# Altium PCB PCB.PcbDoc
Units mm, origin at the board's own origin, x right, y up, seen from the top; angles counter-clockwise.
Board outline 90 x 70 mm, 2 copper layers (Top Layer, Bottom Layer); 116 components, 91 nets, 451 pads, 231 vias.
Unrouted connection lines stored in the file: 2.
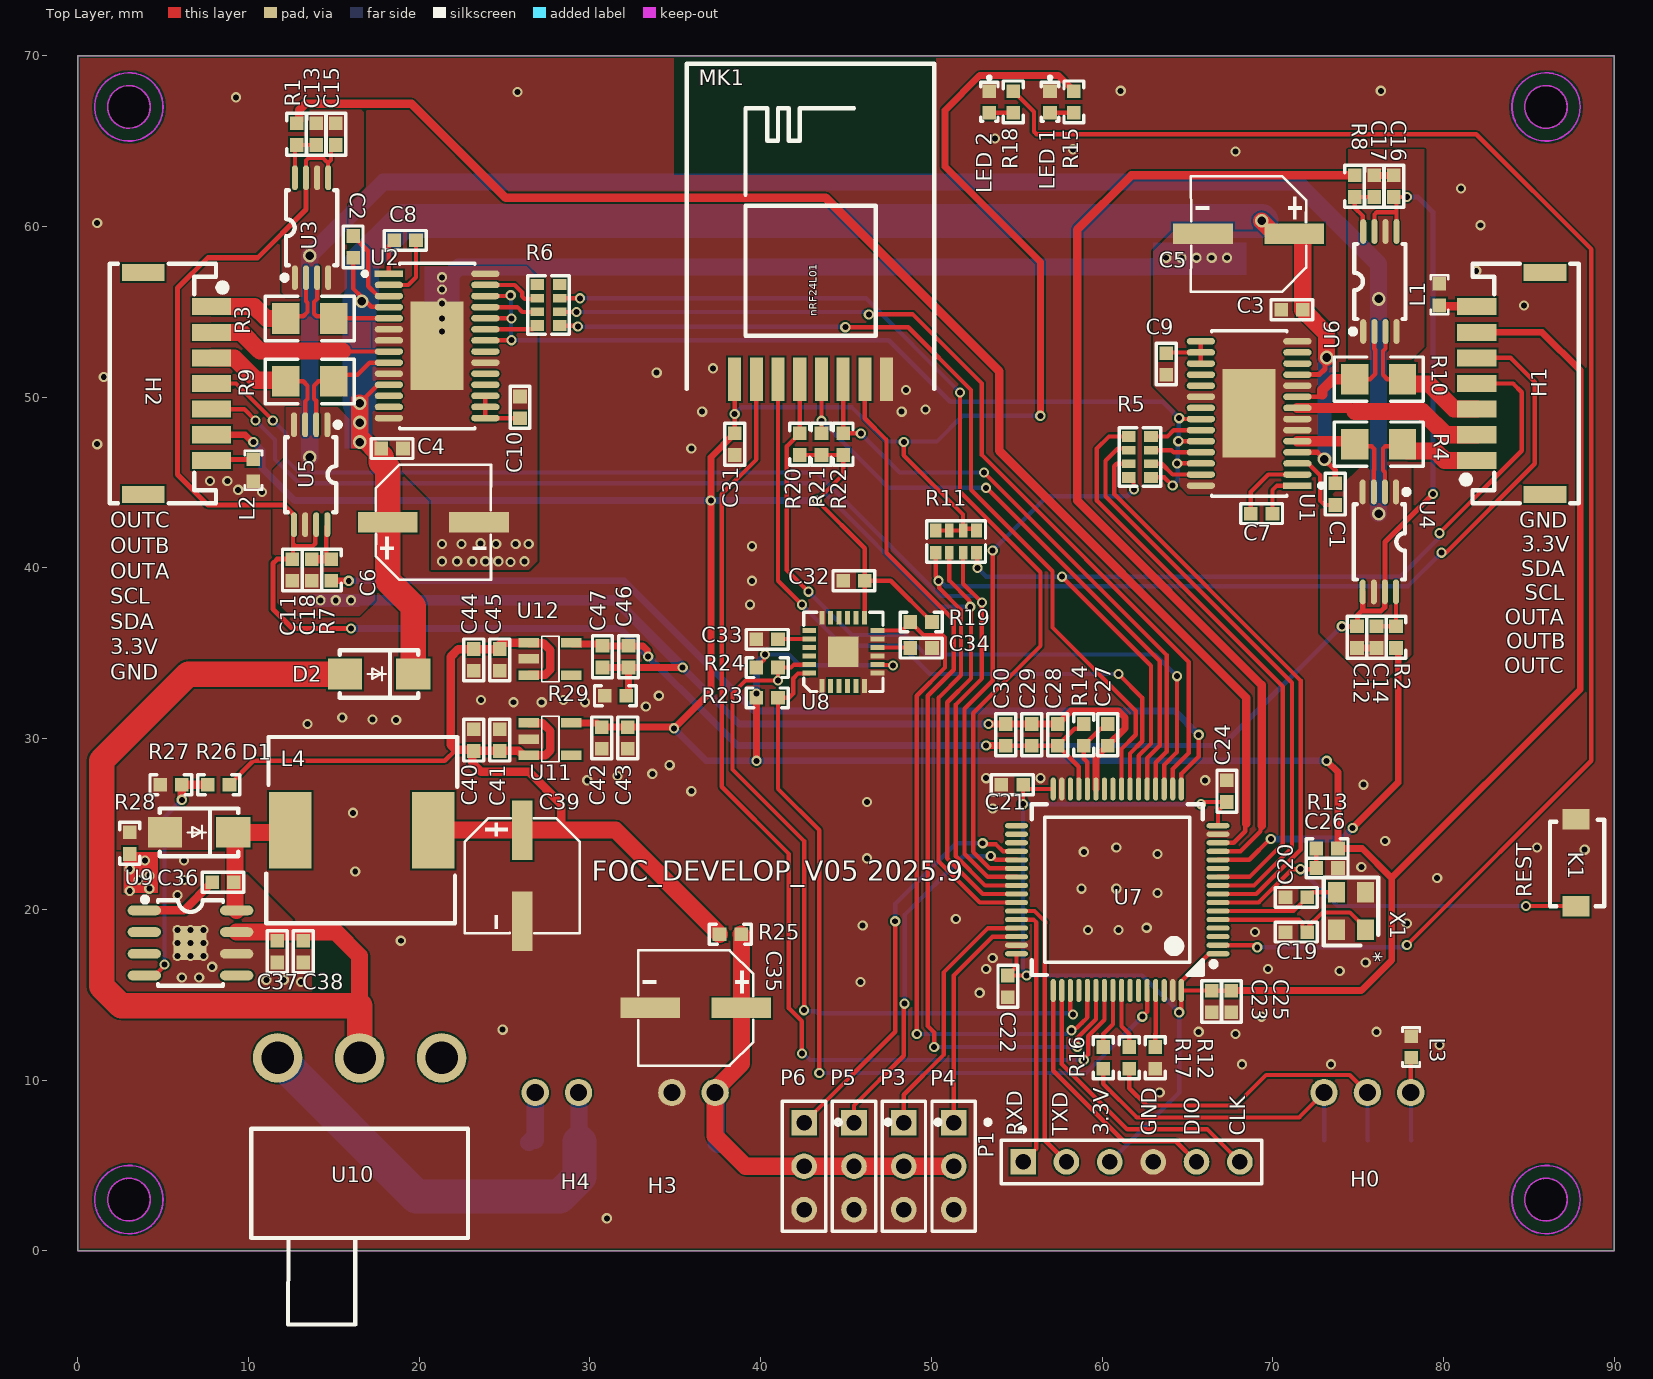
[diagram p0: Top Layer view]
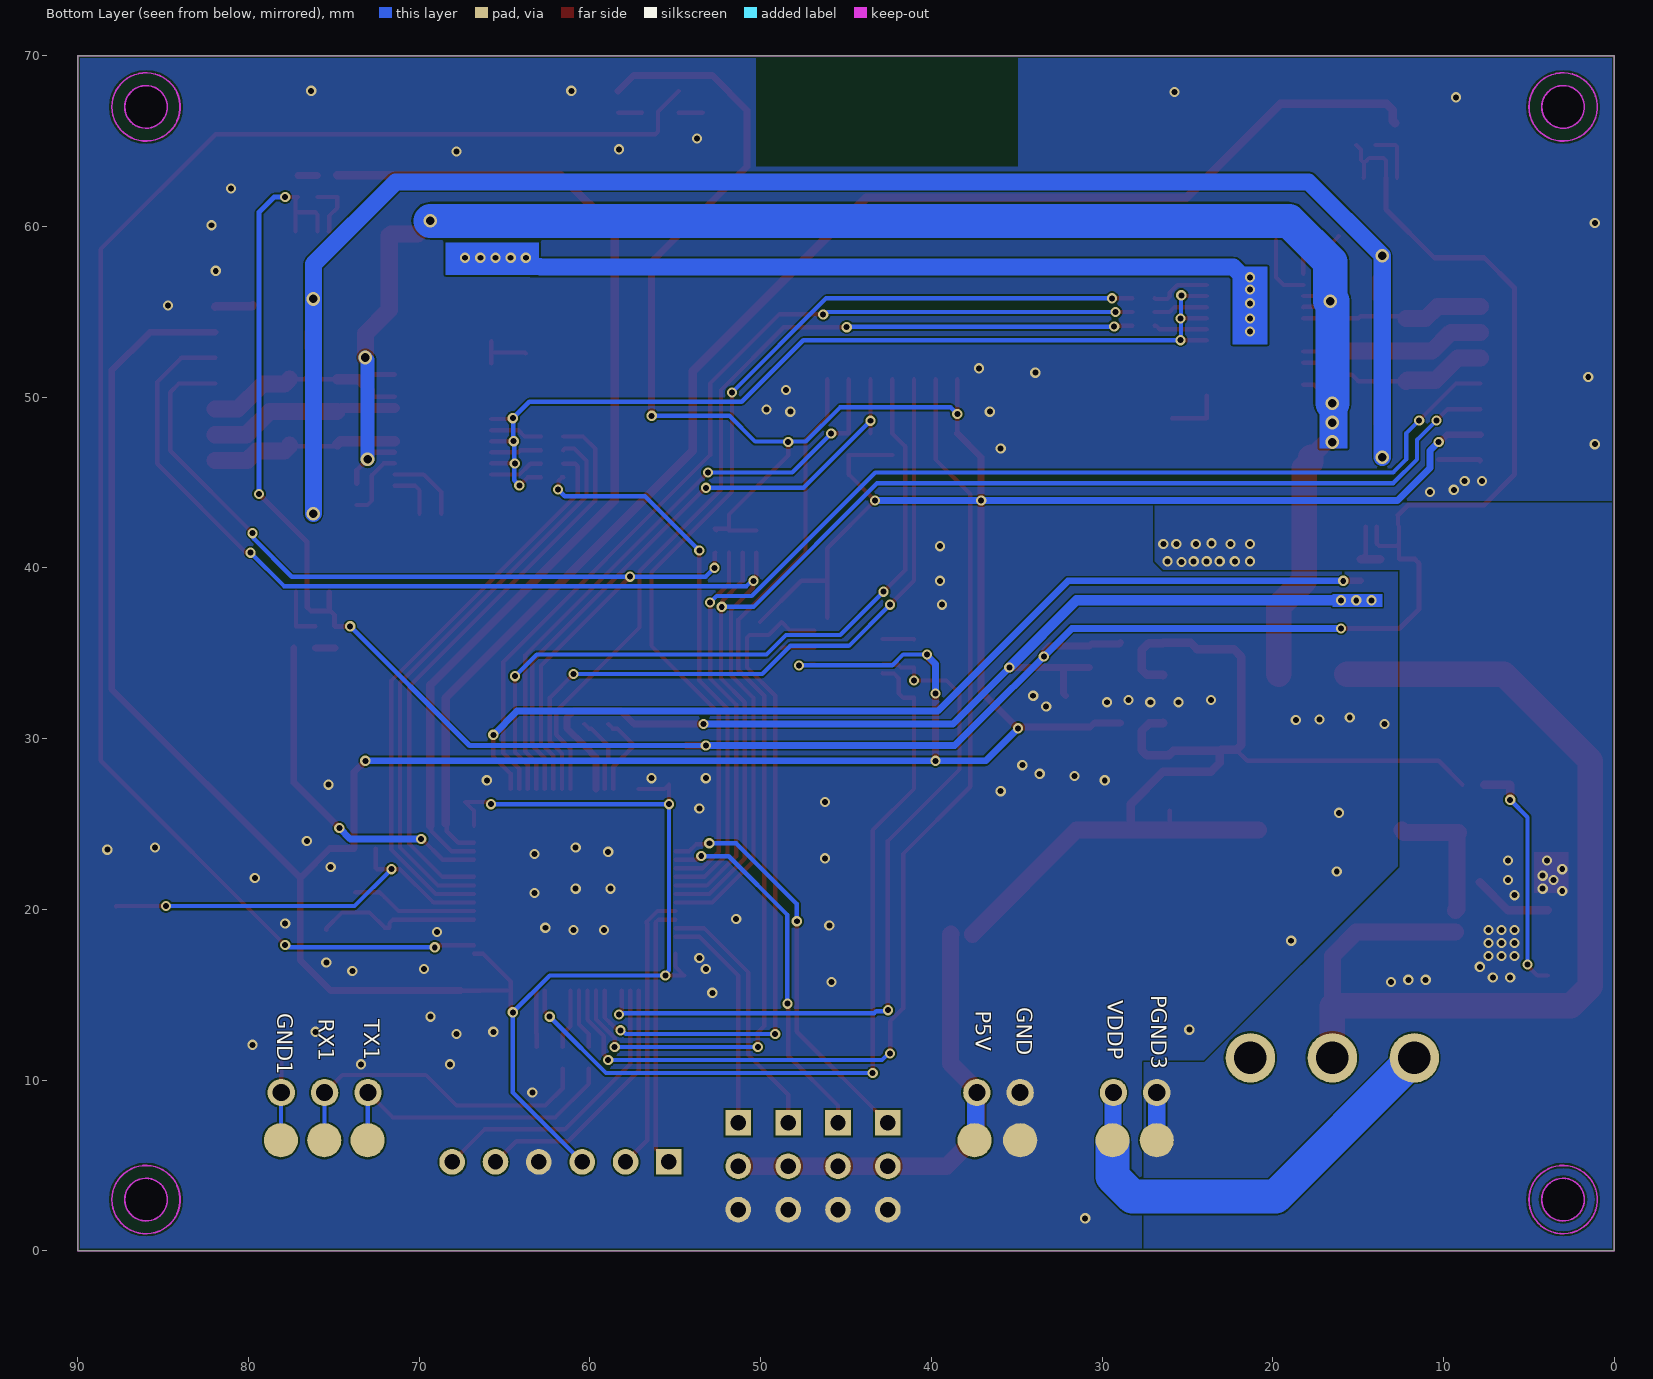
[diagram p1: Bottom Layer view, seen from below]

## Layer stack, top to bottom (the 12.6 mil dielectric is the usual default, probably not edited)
Top Solder: solder mask 0.0102, Solder Resist, Dk 3.5
Top Layer: signal copper 0.0356
Dielectric 1: dielectric 0.32, FR-4, Dk 4.8
Bottom Layer: signal copper 0.0356
Bottom Solder: solder mask 0.0102, Solder Resist, Dk 3.5

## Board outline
0,0 0,70 90,70 90,0
cut-out: 84.75,67 ccw(c86,67) 86,65.75 ccw(c86,67) 87.25,67 ccw(c86,67) 86,68.25 ccw(c86,67)
cut-out: 3,65.75 cw(c3,67) 1.75,67 cw(c3,67) 3,68.25 cw(c3,67) 4.25,67 cw(c3,67)
cut-out: 84.75,67 ccw(c86,67) 86,65.75 ccw(c86,67) 87.25,67 ccw(c86,67) 86,68.25 ccw(c86,67)
cut-out: 1.75,3 ccw(c3,3) 3,1.75 ccw(c3,3) 4.25,3 ccw(c3,3) 3,4.25 ccw(c3,3)
cut-out: 84.75,3 ccw(c86,3) 86,1.75 ccw(c86,3) 87.25,3 ccw(c86,3) 86,4.25 ccw(c86,3)

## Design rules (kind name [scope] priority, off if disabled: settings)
Clearance [All] p1: gap=0.1 ignorepadtopadclearanceinfootprint=FALSE except(0: Arc-Hole Track-Hole SMDPad-Hole THPad-Hole Via-Hole Fill-Hole Poly-Hole Region-Hole Text-Hole; 0.102: Arc-Arc Arc-Track Arc-SMDPad Arc-THPad Track-Track Track-SMDPad Track-THPad SMDPad-SMDPad SMDPad-THPad THPad-THPad; 0.127: Arc-Via Track-Via SMDPad-Via SMDPad-Text THPad-Via Via-Via; 0.254: Arc-Text Track-Text THPad-Text Via-Text Fill-Text Poly-Text Region-Text Text-Text)
HoleSize [All] p1: absolutevalues=TRUE maxlimit=30 minlimit=0.025 maxpercent=80.000 minpercent=20.000
HoleToHoleClearance [All] p1: gap=0.152 allowstackedmicrovias=TRUE
MinimumSolderMaskSliver [All] p1: minsoldermaskwidth=0
PlaneClearance [All] p1: clearance=0.254
PlaneConnect [All] p1: planeconnectstyle=Direct reliefexpansion=0.508 reliefentries=4 reliefconductorwidth=0.254 reliefairgap=0.254
PolygonConnect [All] p1: connectstyle=Direct reliefconductorwidth=0.254 reliefentries=4 polygonreliefangle="90 Angle" airgapwidth=0.254
RoutingVias [All] p1: holewidth=0.711 width=1.27 viastyle="Through Hole" minholewidth=0.3 minwidth=0.5 maxholewidth=30 maxwidth=30
SilkToSilkClearance [All] p1: silktosilkclearance=0
SilkToSolderMaskClearance [IsPad] p1: minsilkscreentomaskgap=0 clearancetoexposedcopper=TRUE
SolderMaskExpansion [All] p1: expansion=0.102 istentingtop=FALSE
Width [All] p1: maxlimit=3 minlimit=0.1 preferedwidth=0.254
23 further rules are at their usual default settings.

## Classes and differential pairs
component class Sheet3-power: C36 C37 C38 C39 C40 C41 C42 C43 C44 C45 C46 C47 D1 D2 H4 L4 PGND3 R26 R27 R28 R29 U9 U10 U11 U12 VDDP
component class Sheet2-sensor: C31 C32 C33 C34 C35 GND H3 MK1 P3 P4 P5 P5V P6 R19 R20 R21 R22 R23 R24 R25 U8
component class Sheet0-MCU: C19 C20 C21 C22 C23 C24 C25 C26 C27 C28 C29 C30 GND1 H0 K1 L3 "LED 1" "LED 2" P1 R12 R13 R14 R15 R16 R17 R18 RX1 TX1 U7 X1
component class Sheet1-driver: C1 C2 C3 C4 C5 C6 C7 C8 C9 C10 C11 C12 C13 C14 C15 C16 C17 C18 H1 H2 L1 L2 R1 R2 R3 R4 R5 R6 R7 R8 R9 R10 R11 U1 U2 U3 U4 U5 U6

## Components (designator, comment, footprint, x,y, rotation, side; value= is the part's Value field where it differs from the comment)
C1 "100nF" CC1608-0603 73.66,44.323 r90 top
C2 "100nF" CC1608-0603 16.129,58.801 r270 top
C3 "100NF" CC1608-0603 71.12,55.118 r180 top
C4 "100NF" CC1608-0603 18.415,46.99 r0 top
C5 "35V 100uF" CAP-SMD_D6.3 68.58,59.563 r180 top
C6 "35V 100uF" CAP-SMD_D6.3 20.831,42.672 r0 top
C7 "0.01uF" CC1608-0603 69.342,43.18 r0 top
C8 "0.01uF" CC1608-0603 19.177,59.182 r180 top
C9 "0.47UF" CC1608-0603 63.754,51.943 r270 top
C10 "0.47UF" CC1608-0603 25.908,49.403 r90 top
C11 "100nF" CC1608-0603 12.573,39.878 r270 top
C12 "100nF" CC1608-0603 74.93,35.941 r270 top
C13 "2.2nF" CC1608-0603 13.97,65.405 r270 top
C14 "2.2nF" CC1608-0603 76.073,35.941 r90 top
C15 "100nF" CC1608-0603 15.113,65.405 r90 top
C16 "100nF" CC1608-0603 77.089,62.357 r90 top
C17 "2.2nF" CC1608-0603 75.946,62.357 r270 top
C18 "2.2nF" CC1608-0603 13.716,39.878 r90 top
C19 "12PF" CC1608-0603 71.374,18.669 r0 top
C20 "12PF" CC1608-0603 71.374,20.701 r0 top
C21 "100NF" CC1608-0603 54.737,27.305 r0 top
C22 "100NF" CC1608-0603 54.483,15.494 r90 top
C23 "100NF" CC1608-0603 66.421,14.605 r90 top
C24 "100NF" CC1608-0603 67.31,26.924 r270 top
C25 "1UF" CC1608-0603 67.564,14.605 r90 top
C26 "100NF" CC1608-0603 73.18,22.424 r180 top
C27 "1UF" CC1608-0603 60.325,30.226 r90 top
C28 "10UF" CC1608-0603 57.404,30.226 r270 top
C29 "1UF" CC1608-0603 55.88,30.226 r270 top
C30 "100NF" CC1608-0603 54.356,30.226 r270 top
C31 "100NF" CC1608-0603 38.481,47.244 r270 top
C32 "100NF" CC1608-0603 45.466,39.243 r180 top
C33 "2.2UF" CC1608-0603 40.386,35.814 r180 top
C34 "100NF" CC1608-0603 49.403,35.306 r180 top
C35 "16V 220uF" CAP-SMD_D6.3 36.198,14.224 r180 top
C36 "0.01uf" CC1608-0603 8.509,21.59 r0 top
C37 "4.7uF 50V" CC1608-0603 11.684,17.526 r270 top
C38 "4.7uF 50V" CC1608-0603 13.208,17.526 r270 top
C39 "16V 220uF" CAP-SMD_D6.3 26.035,21.971 r270 top
C40 "2.2uf" CC1608-0603 23.201,29.914 r270 top
C41 "100nF" CC1608-0603 24.725,29.914 r270 top
C42 "22UF" CC1608-0603 30.694,30.041 r270 top
C43 "100NF" CC1608-0603 32.218,30.041 r270 top
C44 "2.2uf" CC1608-0603 23.201,34.613 r90 top
C45 "100nF" CC1608-0603 24.725,34.613 r90 top
C46 "22UF" CC1608-0603 32.258,34.798 r270 top
C47 "100NF" CC1608-0603 30.734,34.798 r270 top
D1 "B340A" "DO-214 AA" 7.112,24.511 r180 top
D2 "SS34" "DO-214 AA" 17.653,33.782 r180 top
GND "test" test#1 34.798,6.477 r90 bottom
GND1 "test" test#2 78.359,6.255 r180 bottom
H0 "Header_3P_Curved" Header_2_54_3PW 73,9.271 r0 top locked
H1 "ZH 1.5-7P" ZH1.5-7P 83.947,50.8 r90 top locked
H2 "ZH 1.5-7P" ZH1.5-7P 5.842,50.8 r270 top locked
H3 "Header_2P_Curved" Header_2_54_2PW 34.798,9.271 r0 top locked
H4 "Header_2P_Curved" Header_2_54_2PW 26.797,9.271 r0 top locked
K1 "KEY 3*4" "KEY 3*4" 87.757,20.173 r90 top
L1 "68nH 200mA" Inductor-0603 79.756,56.007 r90 top
L2 "68nH 200mA" Inductor-0603 10.287,45.72 r270 top
L3 "68nH 200mA" Inductor-0603 78.105,11.938 r90 top
L4 "22UH" Inductor-1040 12.446,24.638 r90 top
"LED 1" "LED 0603" "LED 0603" 56.951,67.294 r90 top
"LED 2" "LED 0603" "LED 0603" 53.395,67.294 r90 top
MK1 "GT-24-MINI" "GT24 _MINI" 38.481,51.054 r90 top locked
P1 "Header 6" HDR1X6 55.372,5.207 r0 top
P3 "Header 3" HDR1X3 48.387,7.493 r270 top
P4 "Header 3" HDR1X3 51.308,7.493 r270 top
P5 "Header 3" HDR1X3 45.466,7.493 r270 top
P5V "test" test#1 37.465,6.477 r90 bottom
P6 "Header 3" HDR1X3 42.545,7.493 r270 top
PGND3 "test" test#3 28.018,6.445 r0 bottom
R1 "22R" CR1608-0603 12.827,65.405 r270 top
R2 "22R" CR1608-0603 77.216,35.941 r90 top
R3 "0.01R" CR3216-1206 13.589,54.61 r180 top locked
R4 "0.01R" CR3216-1206 76.2,47.244 r0 top locked
R5 "0R" SMD_0603-8P 62.215,46.501 r90 top
R6 "0R" SMD_0603-8P 27.574,55.391 r270 top
R7 "22R" CR1608-0603 14.859,39.878 r90 top
R8 "22R" CR1608-0603 74.803,62.357 r270 top
R9 "0.01R" CR3216-1206 13.589,50.927 r0 top locked
R10 "0.01R" CR3216-1206 76.2,51.054 r180 top
R11 "4.7K" SMD_0603-8P 51.454,41.544 r180 top
R12 "10K" CR1608-0603 63.119,11.303 r90 top
R13 "10K" CR1608-0603 73.18,23.567 r0 top
R14 "10R" CR1608-0603 58.928,30.226 r90 top
R15 "2K" CR1608-0603 58.348,67.294 r90 top
R16 "22R" CR1608-0603 60.071,11.303 r270 top
R17 "22R" CR1608-0603 61.595,11.303 r270 top
R18 "2K" CR1608-0603 54.792,67.294 r90 top
R19 "10K" CR1608-0603 49.403,36.83 r0 top
R20 "10K" CR1608-0603 42.291,47.244 r90 top
R21 "10K" CR1608-0603 43.561,47.244 r90 top
R22 "10K" CR1608-0603 44.831,47.244 r90 top
R23 "10K" CR1608-0603 40.386,32.385 r0 top
R24 "10K" CR1608-0603 40.386,34.163 r0 top
R25 "0R" CR1608-0603 38.227,18.542 r0 top
R26 "10K 1%" CR1608-0603 8.255,27.305 r0 top
R27 "3.24K 1%" CR1608-0603 5.461,27.305 r0 top
R28 "0R" CR1608-0603 3.048,23.876 r270 top
R29 "0R" CR1608-0603 31.496,32.512 r180 top
RX1 "test" test#4 75.438,6.128 r180 bottom
TX1 "test" test#5 72.517,5.747 r180 bottom
U1 "DRV8313PWPR" HTSSOP-28 68.611,49.046 r180 top
U2 "DRV8313PWPR" HTSSOP-28 21.051,53 r0 top
U3 "INA240A1PWR" TSSOP-8 13.697,59.925 r0 top
U4 "INA240A1PWR" TSSOP-8 76.241,41.523 r180 top
U5 "INA240A1PWR" TSSOP-8 13.645,45.46 r180 top locked
U6 "INA240A1PWR" TSSOP-8 76.271,56.775 r0 top
U7 "STM32G431RBT6" LQFP-64 60.889,21.151 r90 top
U8 "MPU6050" "QFN24 - duplicate" 44.843,35.084 r90 top locked
U9 "TPS5430DDAR" SOIC-8-E 6.604,18.034 r270 top
U10 "HX SS12D10G4" SW-TH_3P-SS12D06 16.51,11.303 r0 top locked
U11 "SPX3819M5-L-3.3/TR" SOT23-5 26.416,29.019 r90 top
U12 "SPX3819M5-L-3.3/TR" SOT23-5 26.416,33.718 r90 top
VDDP "test" test#6 29.21,6.572 r0 bottom
X1 "3225_8M" XTAL-3225 73.738,18.796 r90 top

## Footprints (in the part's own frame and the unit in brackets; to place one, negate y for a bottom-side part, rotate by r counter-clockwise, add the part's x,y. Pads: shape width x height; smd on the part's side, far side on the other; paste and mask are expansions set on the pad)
CAP-SMD_D6.3 [mm] "直径6.3mm固态电容"
  rect 3.5x1.2 smd paste+0 mask+0.051: 1(-2.67,0) 2(2.67,0)
  silkscreen extent -3.38,-3.38 3.38,3.38, body extent -3.65,-3.3 3.65,3.3, height 5.9
CC1608-0603 [mm]
  rect 0.8x0.8 smd: 1(-0.635,0) 2(0.635,0)
  silkscreen extent -1.23,-0.58 1.23,0.58, body extent -0.8,-0.4 0.8,0.4, height 0.3
CR1608-0603 [mm]
  rect 0.8x0.8 smd: 1(-0.635,0) 2(0.635,0)
  silkscreen extent -1.23,-0.58 1.23,0.58, body extent -0.8,-0.4 0.8,0.4, height 0.45
CR3216-1206 [mm]
  rect 1.6x1.8 smd: 1(-1.4,0) 2(1.4,0)
  silkscreen extent -2.6,-1.3 2.6,1.3, body extent -1.6,-0.8 1.6,0.8, height 0.6
"DO-214 AA" [mm] "SMB"
  rect 2x1.8 smd: 1(-2,0) 2(2,0)
  silkscreen extent -2.3,-1.4 2.3,1.4, body extent -2.83,-1.8 2.57,1.8, height 2.4
"GT24 _MINI" [mil]
  rect 100x30 smd paste+0 mask+2: 1(0,0) 2(0,-50) 3(0,-100) 4(0,-150) 5(0,-200) 6(0,-250) 7(0,-300) 8(0,-350)
  silkscreen extent -23,-460 728,110, body extent -23,-460 728,110, height 79
HDR1X3 [mm] "Connector; Header; 3 Position"
  rect 1.5x1.5 hole 0.9: 1(0,0)
  round 1.5 hole 0.9: 2(2.54,0) 3(5.08,0)
  silkscreen extent -1.27,-1.27 6.35,2.14, body extent -1.27,-1.27 6.35,1.27, height 8.54
HDR1X6 [mm] "Connector; Header; 6 Position"
  rect 1.5x1.5 hole 0.9: 1(0,0)
  round 1.5 hole 0.9: 2(2.54,0) 3(5.08,0) 4(7.62,0) 5(10.16,0) 6(12.7,0)
  silkscreen extent -1.27,-1.27 13.97,2.04, body extent -1.27,-1.27 13.97,1.27, height 8.54
Header_2_54_2PW [mm] "弯的排针"
  round 1.6 hole 1: 1(0,0) 2(2.54,0)
  body extent -2.52,-7.47 5.18,0.38, height 5.8
Header_2_54_3PW [mm] "3P弯针"
  round 1.6 hole 1: 1(0,0) 2(2.54,0) 3(5.08,0)
  body extent -2.6,-7.48 7.62,0.38, height 5.8
HTSSOP-28 [mm]
  rect 1.655x0.381 smd paste+0 mask+0: 1(-2.825,4.225)
  rrect100% 1.655x0.381 smd paste+0 mask+0: 2(-2.825,3.575) 3(-2.825,2.925) 4(-2.825,2.275) 5(-2.825,1.625) 6(-2.825,0.975) 7(-2.825,0.325) 8(-2.825,-0.325) 9(-2.825,-0.975) 10(-2.825,-1.625) 11(-2.825,-2.275) 12(-2.825,-2.925) 13(-2.825,-3.575) 14(-2.825,-4.225) 15(2.825,-4.225) 16(2.825,-3.575) 17(2.825,-2.925) 18(2.825,-2.275) 19(2.825,-1.625) 20(2.825,-0.975) 21(2.825,-0.325) 22(2.825,0.325) 23(2.825,0.975) 24(2.825,1.625) 25(2.825,2.275) 26(2.825,2.925) 27(2.825,3.575) 28(2.825,4.225)
  rect 3.1x5.18 smd paste-1000 mask+0: 29(0,0)
  silkscreen extent -4.35,-4.85 2.2,4.85, body extent -3.9,-5.1 3.9,5.1, height 0.25
Inductor-0603 [mm]
  rect 0.8x0.8 smd: 1(-0.635,0) 2(0.635,0)
  silkscreen extent -1.14,-0.51 1.14,0.51, body extent -0.8,-0.43 0.8,0.43, height 0.48
Inductor-1040 [mm]
  rect 4.5x2.5 smd: 1(0,0) 2(0,-8.382)
  silkscreen extent -5.46,-9.78 5.46,1.4, body extent -5,-9.39 5,1.01, height 3.9
"KEY 3*4" [mm]
  rect 1.2x1.6 smd: 1(0,0) 2(5.1,0)
  silkscreen extent 0,-1.65 5.08,1.52, body extent 0.25,-1.71 4.7,1.46, height 2.01
"LED 0603" [mm]
  rect 0.8x0.8 smd: 1(-0.635,0) 2(0.635,0)
  silkscreen extent -1.14,-0.51 1.48,0.51, body extent -0.8,-0.4 0.8,0.4, height 0.6
LQFP-64 [mm]
  oval 0.3x1.35 smd paste+0 mask+0.051: 1(-3.75,-5.9) 2(-3.25,-5.9) 3(-2.75,-5.9) 4(-2.25,-5.9) 5(-1.75,-5.9) 6(-1.25,-5.9) 7(-0.75,-5.9) 8(-0.25,-5.9) 9(0.25,-5.9) 10(0.75,-5.9) 11(1.25,-5.9) 12(1.75,-5.9) 13(2.25,-5.9) 14(2.75,-5.9) 15(3.25,-5.9) 16(3.75,-5.9) 33(3.75,5.9) 34(3.25,5.9) 35(2.75,5.9) 36(2.25,5.9) 37(1.75,5.9) 38(1.25,5.9) 39(0.75,5.9) 40(0.25,5.9) 41(-0.25,5.9) 42(-0.75,5.9) 43(-1.25,5.9) 44(-1.75,5.9) 45(-2.25,5.9) 46(-2.75,5.9) 47(-3.25,5.9) 48(-3.75,5.9)
  oval 1.35x0.3 smd paste+0 mask+0.051: 17(5.9,-3.75) 18(5.9,-3.25) 19(5.9,-2.75) 20(5.9,-2.25) 21(5.9,-1.75) 22(5.9,-1.25) 23(5.9,-0.75) 24(5.9,-0.25) 25(5.9,0.25) 26(5.9,0.75) 27(5.9,1.25) 28(5.9,1.75) 29(5.9,2.25) 30(5.9,2.75) 31(5.9,3.25) 32(5.9,3.75) 49(-5.9,3.75) 50(-5.9,3.25) 51(-5.9,2.75) 52(-5.9,2.25) 53(-5.9,1.75) 54(-5.9,1.25) 55(-5.9,0.75) 56(-5.9,0.25) 57(-5.9,-0.25) 58(-5.9,-0.75) 59(-5.9,-1.25) 60(-5.9,-1.75) 61(-5.9,-2.25) 62(-5.9,-2.75) 63(-5.9,-3.25) 64(-5.9,-3.75)
  silkscreen extent -5,-5.79 5,5, body extent -6.05,-6.12 6.1,6.02, height 1.62
"QFN24 - duplicate" [mm]
  rect 0.8x0.3 smd: 1(-2,1.25) 2(-2,0.75) 3(-2,0.25) 4(-2,-0.25) 5(-2,-0.75) 6(-2,-1.25) 13(2,-1.25) 14(2,-0.75) 15(2,-0.25) 16(2,0.25) 17(2,0.75) 18(2,1.25)
  rect 1.8x1.8 smd: 1(0.005,0)
  rect 0.3x0.8 smd: 7(-1.25,-2) 8(-0.75,-2) 9(-0.25,-2) 10(0.25,-2) 11(0.75,-2) 12(1.25,-2) 19(1.25,2) 20(0.75,2) 21(0.25,2) 22(-0.25,2) 23(-0.75,2) 24(-1.25,2)
  silkscreen extent -2.32,-2.32 2.32,2.32, body extent -2,-2 2.01,2, height 0.9
SMD_0603-8P [mm]
  rect 0.65x0.8 smd paste+0 mask+0.051: 1(-1.2,-0.65) 4(1.2,-0.65) 5(1.2,0.65) 8(-1.2,0.65)
  rect 0.5x0.8 smd paste+0 mask+0.051: 2(-0.4,-0.65) 3(0.4,-0.65) 6(0.4,0.65) 7(-0.4,0.65)
  silkscreen extent -1.71,-1.22 1.71,1.22, body extent -1.6,-0.8 1.6,0.8, height 0.5
SOIC-8-E [mil]
  oval 22.38x76.78 smd paste+0 mask+2: 1(-75,-106.5) 2(-25,-106.5) 3(25,-106.5) 4(75,-106.5) 5(75,106.5) 6(25,106.5) 7(-25,106.5) 8(-75,106.5)
  rect 78.74x76.78 smd paste+0 mask+2: 9(0,-1)
  silkscreen extent -106,-111 98,75, body extent -98,-125 98,120, height 69
SOT23-5 [mm] "适用于MIC5205"
  rect 0.55x1.2 smd: 1(1.905,0) 2(0.955,0) 3(0.005,0) 4(0.005,-2.5) 5(1.905,-2.5)
  silkscreen extent -0.38,-1.78 2.29,-0.76, body extent -0.6,-2.82 2.5,0.38, height 1.45
SW-TH_3P-SS12D06 [mm]
  round 2.9 hole 1.9 paste+0 mask+0.051: 1(-4.8,0) 2(0,0) 3(4.8,0)
  silkscreen extent -6.35,-15.62 6.35,-4.15, body extent -6.35,-15.68 6.35,-4.19, height 6.7
test#1 [mm]
  round 2 smd: 0(0,0)
test#2 [mm]
  round 2 smd: 0(0.259,0.222)
test#3 [mm]
  round 2 smd: 0(-1.221,-0.032)
test#4 [mm]
  round 2 smd: 0(-0.122,0.349)
test#5 [mm]
  round 2 smd: 0(-0.503,0.73)
test#6 [mm]
  round 2 smd: 0(0.176,0.095)
TSSOP-8 [mm]
  oval 0.353x1.454 smd: 1(-0.975,-2.927) 2(-0.325,-2.927) 3(0.325,-2.927) 4(0.975,-2.927) 5(0.975,2.927) 6(0.325,2.927) 7(-0.325,2.927) 8(-0.975,2.927)
  silkscreen extent -1.73,-3.08 1.5,2.2, body extent -1.43,-3.17 1.57,3.11, height 1.09
XTAL-3225 [mm]
  rect 1.2x1 smd: 1(0,-1.7) 2(2.2,-1.7) 3(2.2,0) 4(0,0)
  silkscreen extent -0.91,-2.44 3.07,0.76, body extent -0.43,-2.15 2.77,0.35, height 0.61
ZH1.5-7P [mm]
  rect 1x2.3 smd paste+0 mask+0.05: 1(-4.5,2) 2(-3,2) 3(-1.5,2) 4(0,2) 5(1.5,2) 6(3,2) 7(4.5,2)
  rect 1x2.5 smd paste+0 mask+0.05: 8(6.5,-2) 9(-6.5,-2)
  silkscreen extent -7.02,-3.97 7.02,3.04, body extent -6.96,-4.36 6.96,2.69, height 4

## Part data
C1 C2 C3 C4 C7 C8 C9 C10 C11 C12 C13 C14 C15 C16 C17 C18 C19 C20 C21 C22 C23 C24 C25 C26 C27 C28 C29 C30 C40 C41 C44 C45: library part "Cap Chip 0603", "0603封装的电容"
C5 C6 C35 C39: library part "Cap ECAP SMD", "铝点解电容", BOM_Manufacturer=PANASONIC, BOM_Manufacturer Part=EEEFP1C681AP
C31 C32 C33 C34 C36 C37 C38 C42 C43 C46 C47: library part "Chip capacitor", "贴片电容"
D1: "40V 3A 550mV@3A", BOM_JLCPCB Part Class="Extended Part", BOM_Manufacturer=MDD
D2: "肖特基二极管"
GND GND1 P5V PGND3 RX1 TX1 VDDP: "测试点"
H0: "弯的3P排针"
H1 H2: "ZH1.5-7P 间距1.5的贴片连接座"
H3 H4: "弯的2P排针"
K1: "轻触开关按键"
L1 L2 L3: library part Inductor-0603, "贴片电感 0603封装"
L4: library part Inductor-1040, "1040封装 一体成型 贴片 功率电感"
MK1: "工业级GT-24数传无线模块 2.4G NRF24L01&PA+LNA", JLCPCB Part Class="Extended Part", Manufacturer=Ashining(泽耀科技), Manufacturer Part=AS01-ML01S
P1: "Header, 6-Pin"
P3 P4 P5 P6: "Header, 3-Pin"
R1 R2 R7 R8 R12 R13 R14 R15 R16 R17 R18 R28 R29: library part "Resistor Chip 0603", "0603封装电阻"
R3 R4 R9 R10: library part "Resistor Chip 1206", "1206封装电阻"
R5 R6 R11: library part "Resistor Chip 0603_1206", "0603封装电阻"
R19 R20 R21 R22 R23 R24 R25 R26 R27: library part "Chip resistor", "贴片电阻"
U1 U2: library part DRV8313, "独立控制的半 H 桥驱动器,主要用于驱动一个三项无刷电机IC MOTOR DRIVER 8V-60V 28HTSSOP", Case/Package=HTSSOP, Max Operating Temperature=125°C, Max Supply Voltage=60V, Min Operating Temperature=-40°C, Min Supply Voltage=8V, Output Current=1.75A, Package Quantity=2000
U3 U4 U5 U6: "超精密电流检测放大器"
U7: JLCPCB Part Class="Extended Part", Manufacturer=ST(意法半导体)
U8: "陀螺仪"
U9: "宽电压DCDC降压IC"
U10: library part SW-TH_3P-SS12D06, BOM_JLCPCB Part Class="Extended Part", BOM_Manufacturer=hanxia(韩下)
U11 U12: "LDO 3.3V , SOT-23-5 500ma"
X1: library part "XTAL 3225", "3225封装的晶振"

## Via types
v1: diameter 0.6, hole 0.35, Top Layer to Bottom Layer, tented both sides, 220 vias
v2: diameter 0.8, hole 0.5, Top Layer to Bottom Layer, tented both sides, 11 vias

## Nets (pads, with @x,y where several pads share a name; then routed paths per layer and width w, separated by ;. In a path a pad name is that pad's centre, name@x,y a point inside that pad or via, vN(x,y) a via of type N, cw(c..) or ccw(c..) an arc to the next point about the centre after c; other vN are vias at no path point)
3.3V: C21.2 C22.2 C23.2 C24.2 C25.2 C31.1 C32.1 C42.1 C43.1 H1.6 H2.6 MK1.1 P1.3 R11.1 R11.2 R11.3 R11.4 R13.2 R15.2 R19.2 R20.1 R21.1 R22.1 R23.1 R24.1 U7.1 U7.16 U7.32 U7.48 U7.64 U8.8 U8.13 U11.5 | length 318.9
  Top Layer w0.254: C31.1 MK1.1 ; R24.1 40.193,34.605 ; R20.1 R21.1 R22.1 44.831,45.466 v1(43.307,43.942) 46.101,41.148 C32.1 ; U8.13 46.093,39.235 C32.1 ; U8.8 47.094,34.334 47.116,34.312 47.73,34.312 v1(47.752,34.29) ; v1(48.387,47.371) 48.387,46.591 51.854,43.124 51.854,42.342 51.905,42.291 52.705,42.291 R11.1@52.608,42.194 ; R19.2 47.625,39.243 C32.1 ; R11.4 R11.3 R11.2 ; U7.48 54.989,16.635 C22.2 v1(55.58,16.129) ; v1(55.372,26.162) C21.2 55.626,27.051 U7.32 ; v1@64.639,14.186 U7.64 ; v1@66.007,26.289 C24.2 66.789,25.768 U7.16 ; U7.1 66.264,17.401 64.639,15.776 U7.64 ; C25.2 C23.2 66.41,15.251 U7.64
  Top Layer w0.4: H2.6 9.804,47.8 10.233,47.371 v1(10.287,47.371) ; U11.5 30.445,30.924 C42.1 34.802,30.676 34.871,30.607 v1(34.925,30.607) 37.084,32.766 37.084,46.482 C31.1 ; v1(39.751,28.702) R23.1 v1(39.751,32.639) ; v1@56.388,48.895 56.388,57.912 50.8,63.5 50.8,66.802 52.832,68.834 57.443,68.834 R15.2 ; C25.2 75.184,15.24 76.962,17.018 76.962,21.844 ; v1(73.152,28.702) 73.815,28.039 R13.2 75.239,23.567 76.962,21.844 ; H1.6 85.773,53.8 88.011,51.562 88.011,32.893 76.962,21.844
  Bottom Layer w0.254: v1(38.481,49.022) 38.862,49.403 45.356,49.403 47.356,47.402 50.323,47.402 51.832,48.911 v1(56.382,48.911) ; v1(40.259,34.925) 41.656,34.925 42.291,34.29 v1(47.752,34.29) ; v1(55.58,16.129) 55.58,16.223 55.372,16.431 v1(55.372,26.162) v1(65.786,26.162) ; v1@55.626,16.129 62.357,16.129 v1(64.516,13.97) 64.516,9.271 P1.3
  Bottom Layer w0.4: v1(10.287,47.371) 10.795,46.863 10.795,45.847 12.7,43.942 v1(37.084,43.942) ; v1(34.925,30.607) 36.83,28.702 v1(73.152,28.702) ; v1@37.118,43.942 v1(43.307,43.942) ; v1(39.751,32.639) 39.751,34.363 40.259,34.871 v1(40.259,34.925)
5V: C39.1 C40.2 C41.2 C44.2 C45.2 L4.2 R25.1 R26.2 U11.1 U11.3 U12.1 U12.3 | length 65.9
  Top Layer w0.254: R26.2 10.287,28.702 21.502,28.702 22.137,29.337 ; C39.1 C39.1@26.035,25.791
  Top Layer w0.5: U11.1 26.441,30.899 27.228,30.899 27.686,30.441 27.686,29.317 27.393,29.025 U11.3 26.091,29.025 25.837,29.279 C41.2 C40.2 C40.2@23.114,29.192 ; U12.3 26.441,33.749 27.393,33.749 27.686,34.041 27.686,35.179 27.267,35.598 26.441,35.598 U12.1 24.821,35.623 24.446,35.248 C44.2 22.294,35.248 21.844,34.798 21.844,29.63 22.137,29.337 23.051,29.337 23.114,29.274 C40.2@23.114,29.192 ; 28.321,24.641 28.321,26.162 26.416,28.067 23.622,28.067 23.114,28.575 C40.2@23.114,29.192
  Top Layer w1: L4.2 26.032,24.638 C39.1 28.321,24.641 31.493,24.641 R25.1
5V_M: C35.1 H3.2 P3.2 P4.2 P5.2 P5V.0 P6.2 R25.2 | length 30.3
  Top Layer w1: R25.2 38.868,18.536 C35.1 38.868,10.963 37.338,9.433 H3.2 37.338,6.731 39.116,4.953 P6.2 P5.2 P3.2 P4.2
  Bottom Layer w1: H3.2 37.401,9.207 37.401,6.286 P5V.0@37.465,6.223
ADC1_IN1: R2.1 U7.12 | length 20.3
  Top Layer w0.254: U7.12 68.621,22.901 69.843,24.123 v1(69.879,24.123)
  Top Layer w0.4: v1(74.676,24.765) 77.343,27.432 R2.1@77.343,35.306
  Bottom Layer w0.4: v1(69.879,24.123) 69.887,24.13 74.038,24.13 74.673,24.765 v1(74.676,24.765)
ADC1_IN2: R8.1 U7.13 | length 60.3
  Top Layer w0.254: U7.13 68.105,23.401 69.276,24.572 69.276,24.826 69.342,24.892
  Top Layer w0.5: 69.342,24.892 69.342,33.147 58.547,43.942 58.547,59.817 61.722,62.992 R8.1
ADC1_IN3: R1.1 U7.14 | length 83.3
  Top Layer w0.254: U7.14 67.716,23.901 68.387,24.572 68.387,24.953 68.453,25.019
  Top Layer w0.5: R1.1 12.977,66.19 12.977,66.825 13.335,67.183 19.558,67.183 25.063,61.678 43.815,61.678 53.975,51.518 53.975,46.863 68.453,32.385 68.453,25.019
ADC1_IN4: R7.1 U7.17 | length 58.1
  Top Layer w0.254: U7.17 64.639,27.936 65.659,28.956 v1(65.659,30.226)
  Top Layer w0.4: R7.1 v1(15.875,39.243)
  Bottom Layer w0.4: v1(15.875,39.243) 32.004,39.243 39.624,31.623 64.262,31.623 v1(65.659,30.226)
AGND: C11.2 C12.2 C13.1 C14.1 C15.2 C16.2 C17.1 C18.1 C27.1 C28.1 C29.1 C30.1 C46.2 C47.2 R29.1 U3.1 U3.4 U3.6 U4.1 U4.4 U4.6 U5.1 U5.4 U5.6 U6.1 U6.4 U6.6 U7.27 | length 155.2
  Top Layer w0.4: C47.2 C46.2 ; R29.1 32.258,32.639 C46.2 ; v1(35.433,34.163) C46.2 ; v1(53.34,30.861) C30.1 C29.1 C28.1 58.166,31.623 60.96,31.623 61.341,31.242 61.341,30.607 C27.1 59.639,28.905 U7.27 ; C12.2 C14.1 ; C17.1 C16.2
  Bottom Layer w0.4: v1(35.433,34.163) 38.735,30.861 v1(53.34,30.861)
  Bottom Layer w0.6: v1(16.002,38.1) 31.496,38.1 v1(35.433,34.163)
  Bottom Layer w1: v2(13.589,46.482) v2(13.589,58.293) 17.907,62.611 71.374,62.611 76.2,57.785 v2(76.2,55.753) v2(76.2,43.18)
  other v1: 14.224,38.1 15.113,38.1
BOOT0: R12.2 U7.61 | length 3.3
  Top Layer w0.254: R12.2 63.119,12.7 63.139,12.72 U7.61
DRV_EN: R5.8 U7.39 | length 32.7
  Top Layer w0.254: v1(53.594,41.021) 53.594,33.401 51.943,31.75 51.943,23.255 53.297,21.901 U7.39 ; R5.8 61.64,45.301 61.838,45.103 61.838,44.625 v1(61.867,44.596)
  Bottom Layer w0.254: v1(53.594,41.021) 56.769,44.196 61.468,44.196 v1(61.867,44.596)
GND: "LED 1.2" "LED 2.2" C19.1 C20.1 C21.1 C22.1 C23.1 C24.1 C25.1 C26.1 C31.2 C32.2 C33.2 C34.1 C35.2 C39.2 C40.1 C41.1 C42.2 C43.2 C44.1 C45.1 D1.2 GND.0 H3.1 K1.2 L1.2 L2.2 L3.2 MK1.8 P1.4 P3.3 P4.3 P5.3 P6.3 R12.1 R27.1 R28.1 R29.2 U7.15 U7.31 U7.47 U7.63 U8.1 U8.6 U8.7 U8.9 U8.11 U8.18 U11.2 U12.2 X1.2 X1.4
  other v1: 30.988,1.905 63.373,9.271 68.199,10.922 73.406,10.922 79.756,12.065 67.818,12.7 65.659,12.827 76.073,12.827 24.892,12.954 69.342,13.716 52.832,15.113 45.847,15.748 73.914,16.383 53.213,16.51 69.723,16.51 75.438,16.891 53.594,17.145 18.923,18.161 68.961,18.669 59.182,18.796 60.96,18.796 62.611,18.923 45.974,19.05 77.851,19.177 51.435,19.431 63.246,20.955 58.801,21.209 60.833,21.209 79.629,21.844 16.256,22.225 75.184,22.479 46.228,22.987 63.246,23.241 58.928,23.368 88.265,23.495 60.833,23.622 85.471,23.622 76.581,24.003 16.129,25.654 53.594,25.908 46.228,26.289 35.941,26.924 75.311,27.305 29.845,27.559 66.04,27.559 53.213,27.686 56.388,27.686 31.623,27.813 33.655,27.94 34.671,28.448 13.462,30.861 18.654,31.088 17.272,31.115 15.494,31.242 33.274,31.877 25.527,32.131 27.178,32.131 29.718,32.131 23.622,32.258 28.448,32.258 34.036,32.512 39.37,37.846 39.497,39.243 39.497,41.275 10.795,44.45 9.398,44.577 7.747,45.085 8.763,45.085 35.941,46.99 1.143,47.244 36.576,49.149 48.26,49.149 49.657,49.276 48.514,50.419 1.524,51.181 33.909,51.435 37.211,51.689 84.709,55.372 81.915,57.404 82.169,60.071 1.143,60.198 81.026,62.23 67.818,64.389 58.293,64.516 53.721,65.151 9.271,67.564 25.753,67.876 61.087,67.945 76.327,67.945
GT24_CE: MK1.2 U7.55 | length 63.5
  Top Layer w0.254: MK1.2 39.751,46.355 37.719,44.323 37.719,27.178 41.656,23.241 41.656,14.203 42.418,13.441 v1(42.418,11.557) ; v1(58.928,11.176) 58.928,11.244 59.182,11.498 59.182,12.573 60.139,13.53 U7.55
  Bottom Layer w0.254: v1(42.418,11.557) 42.512,11.557 42.893,11.176 v1(58.928,11.176)
GT24_IRQ: MK1.7 U7.54 | length 54.2
  Top Layer w0.254: MK1.7 46.101,48.768 47.371,47.498 47.371,40.894 51.308,36.957 51.308,34.036 49.784,32.512 49.784,13.168 50.165,12.787 v1(50.165,11.938) ; v1(58.547,11.938) 58.547,12.471 59.639,13.562 U7.54
  Bottom Layer w0.254: v1(50.165,11.938) v1(58.547,11.938)
HSE_I: C19.2 U7.5 X1.1 | length 9.9
  Top Layer w0.254: U7.5 71.531,19.401 71.736,19.196 71.736,18.942 71.755,18.923 72.009,18.923 72.906,19.82 74.514,19.82 75.438,18.896 X1.1
HSE_O: C20.2 U7.6 X1.3 | length 7.4
  Top Layer w0.254: U7.6 71.209,19.901 C20.2 72.304,20.996 X1.3
I2C1_SCL: R24.2 U7.51 U8.23 | length 43.2
  Top Layer w0.254: v1(42.545,14.097) 42.545,24.003 38.354,28.194 38.354,32.639 39.116,33.401 v1(41.021,33.401) R24.2 41.783,34.163 41.954,34.334 U8.23 ; U7.51 58.139,14.091 58.293,13.937 v1(58.293,13.843)
  Bottom Layer w0.254: v1(42.545,14.097) 42.608,14.034 43.226,14.034 43.353,13.906 58.229,13.906 v1(58.293,13.843)
I2C1_SDA: R23.2 U7.60 U8.24 | length 47.9
  Top Layer w0.254: U8.24 42.82,33.811 42.193,33.811 41.91,33.528 41.91,32.639 41.656,32.385 R23.2 41.021,27.056 43.434,24.643 v1(43.434,10.414) ; v1(62.357,13.716) 62.639,13.998 U7.60
  Bottom Layer w0.254: v1(43.434,10.414) 59.055,10.414 61.883,13.242 v1(62.357,13.716)
I2C2_SCL: H1.4 R11.8 U7.22 | length 57.4
  Top Layer w0.254: R11.8 52.679,40.868 52.679,40.031 v1(52.705,40.005) ; v1(57.647,39.486) 58.166,38.968 62.865,34.269 62.865,29.718 62.139,28.992 U7.22 ; v1(79.756,42.037) 84.582,46.863 84.582,50.292 84.074,50.8 H1.4
  Bottom Layer w0.254: v1(52.705,40.005) 53.224,39.486 77.459,39.486 79.69,41.717 79.69,41.971 v1(79.756,42.037)
I2C2_SDA: H1.5 R11.5 U7.42 | length 71.6
  Top Layer w0.254: R11.5 50.254,39.501 50.419,39.337 v1(50.419,39.243) 50.456,39.206 50.456,38.825 51.741,37.54 51.741,33.707 50.419,32.385 50.419,22.814 52.832,20.401 U7.42 ; v1(79.883,40.894) 80.137,40.894 85.345,46.102 85.345,50.893 83.937,52.3 H1.5
  Bottom Layer w0.254: v1(50.419,39.243) 50.513,39.243 50.823,38.932 77.921,38.932 v1(79.883,40.894)
I2C3_SCL: H2.4 R11.7 U7.40 | length 74.5
  Top Layer w0.254: H2.4 9.271,50.8 v1(11.43,48.641) ; R11.7 51.854,39.078 v1(52.959,37.973) 52.959,33.528 51.435,32.004 51.435,23.114 53.148,21.401 U7.40
  Bottom Layer w0.254: v1(11.43,48.641) 12.192,47.879 12.192,46.355 12.954,45.593 43.286,45.593 50.525,38.354 52.578,38.354 v1(52.959,37.973)
I2C3_SDA: H2.5 R11.6 U7.41 | length 73.8
  Top Layer w0.254: H2.5 9.755,49.3 v1(10.414,48.641) ; R11.6 51.054,39.255 52.228,38.081 52.228,37.768 v1(52.278,37.718) ; v1@52.295,37.726 52.324,37.697 52.324,33.528 50.927,32.131 50.927,22.987 53.013,20.901 U7.41
  Bottom Layer w0.254: v1(10.414,48.641) 11.557,47.498 11.557,46.355 12.954,44.958 43.18,44.958 50.42,37.718 v1(52.278,37.718)
LED0: R18.2 U7.2 | length 94.8
  Top Layer w0.254: R18.2 56.007,66.714 56.007,65.554 56.156,65.405 81.915,65.405 88.646,58.674 88.646,28.702 v1(77.851,17.907) ; U7.2 68.967,17.901 v1(69.088,17.78)
  Bottom Layer w0.254: v1(69.088,17.78) 77.63,17.78 77.757,17.907 v1(77.851,17.907)
M1_CS1: R4.1 U1.5 U4.3 | length 7.2
  Top Layer w0.254: R4.1 74.927,47.117 75.797,47.117 75.946,46.968 75.946,45.75 75.916,45.72 U4.3
  Top Layer w0.6: U1.5 74.623,47.421 R4.1
M1_CS2: H1.2 U1.8 | length 11.2
  Top Layer w0.6: U1.8 74.581,49.371 74.803,49.149
  Top Layer w1: 74.803,49.149 78.774,49.149 80.123,47.8 H1.2
M1_CS3: R10.2 U1.9 U6.2 | length 7.8
  Top Layer w0.254: U1.9 72.754,50.021 72.898,50.165 ; R10.2 75.692,51.054 76.002,51.364 76.002,52.776 75.946,52.832 U6.2
  Top Layer w0.6: 72.898,50.165 72.898,50.419 73.533,51.054 R10.2
M1_IN1: R5.2 U1.27 | length 3.2
  Top Layer w0.254: R5.2 63.5,46.101 64.13,45.471 U1.27
M1_IN2: R5.3 U1.25 | length 3
  Top Layer w0.254: R5.3 64.061,46.901 64.191,46.771 U1.25
M1_IN3: R5.4 U1.23 | length 3.1
  Top Layer w0.254: R5.4 63.83,47.701 64.2,48.071 U1.23
M2_CS1: R3.1 U2.5 U3.3 | length 6.7
  Top Layer w0.254: U3.3@14.041,57.017 U3.3 14.022,55.753 13.843,55.574 13.843,54.886 13.992,54.737 14.862,54.737 R3.1 15.004,54.625 U2.5
M2_CS2: H2.2 U2.8 | length 10.8
  Top Layer w0.254: 15.494,52.705 15.524,52.675 U2.8
  Top Layer w1: H2.2 9.573,53.8 10.668,52.705 15.494,52.705
M2_CS3: R9.2 U2.9 U5.2 | length 7.3
  Top Layer w0.254: U5.2 13.97,49.784 13.843,49.911 13.843,50.673 14.097,50.927 R9.2 15.37,51.308 16.383,51.308 17.1,52.025 U2.9
M2_IN1: R6.2 U2.27 | length 3.5
  Top Layer w0.254: U2.27 25.594,56.575 26.035,56.134 26.035,55.902 26.184,55.753 26.886,55.753 R6.2
M2_IN2: R6.3 U2.25 | length 3.2
  Top Layer w0.254: U2.25 25.751,55.275 26.035,54.991 R6.3
M2_IN3: R6.4 U2.23 | length 3.1
  Top Layer w0.254: U2.23 26.633,53.975 26.849,54.191 R6.4
M_EN: R5.1 U1.22 U1.24 U1.26 U2.22 U2.24 U2.26 | length 57.9
  Top Layer w0.254: U2.22 v1@25.4,53.325 ; U2.24 25.385,54.625 v1(25.4,54.61) ; U2.26 25.318,55.925 v1(25.359,55.966) v1@25.4,56.007 ; R5.1 63.646,45.301 64.116,44.831 v1(64.135,44.831) ; v1@64.389,47.498 v1(64.466,47.421) U1.24 ; v1(64.399,46.111) 64.409,46.121 U1.26 ; v1(64.516,48.768) 64.563,48.721 U1.22
  Bottom Layer w0.254: v1(25.359,55.966) 25.38,55.946 25.38,54.61 25.38,53.36 v1(25.4,53.34) 47.498,53.34 51.111,49.727 63.557,49.727 v1(64.516,48.768) 64.491,48.743 64.491,47.446 v1(64.466,47.421) 64.433,47.387 64.433,45.129 v1(64.135,44.831)
M_PWR: C1.2 C2.2 C3.1 C4.1 C5.1 C6.1 D2.1 U1.4 U1.11 U2.4 U2.11 | length 108.3
  Top Layer w0.254: C2.2 16.129,56.363 16.637,55.855 v2(16.637,55.626) 16.866,55.626 17.193,55.299 18.201,55.299 U2.4 ; v2(16.51,49.647) 17.588,50.725 U2.11
  Top Layer w0.3: U1.4 72.609,46.771 v2(73.025,46.355) 73.66,45.72 C1.2 ; U1.11 72.722,51.321 73.056,51.655 73.056,52.228 v2(73.152,52.324)
  Top Layer w1: v2(16.51,49.647) 16.51,47.752 17.78,46.482 ; v2(69.342,60.325) 69.342,60.321 70.1,59.563 71.655,59.563 71.755,59.463 C3.1 73.152,53.721 v2(73.152,52.324)
  Top Layer w1.5: 17.78,46.482 17.78,46.203 18.161,45.822 18.161,39.243 19.653,37.751 D2.1
  Bottom Layer w0.8: v2(73.025,46.355) 73.025,52.197 v2(73.152,52.324)
  Bottom Layer w2: v2(16.51,49.647) 16.51,55.626 v2(16.637,55.626) 16.637,57.912 19.05,60.325 v2(69.342,60.325)
  other v2: 16.51,47.371 16.51,48.514
MPU_INT: R19.1 U7.53 U8.12 | length 40
  Top Layer w0.254: U8.12 48.272,36.334 R19.1 49.53,36.068 50.651,36.068 50.8,35.919 50.8,34.163 49.149,32.512 v1(49.149,12.7) ; 58.521,13.055 58.805,13.339 59.139,13.673 U7.53
  Bottom Layer w0.254: v1(49.149,12.7) 57.899,12.7 58.113,12.913 v1(58.207,12.913)
NetC1_1: C1.1 U1.3 | length 4.1
  Top Layer w0.254: U1.3 72.074,46.121 72.771,45.424 72.771,43.942 73.025,43.688 C1.1
NetC2_1: C2.1 U2.3 | length 4.8
  Top Layer w0.254: C2.1 17.018,58.547 17.018,56.495 17.588,55.925 U2.3
NetC7_1: C7.1 U1.2 | length 4.4
  Top Layer w0.254: C7.1 68.707,44.45 69.728,45.471 U1.2
NetC7_2: C7.2 U1.1 | length 2.9
  Top Layer w0.254: C7.2 69.977,44.557 70.241,44.821 U1.1
NetC8_1: C8.1 U2.2 | length 3.9
  Top Layer w0.254: U2.2 19.364,56.575 19.812,57.023 C8.1
NetC8_2: C8.2 U2.1 | length 2.1
  Top Layer w0.254: U2.1 18.225,58.865 C8.2
NetC13_2: C13.2 R1.2 U3.8 | length 3.1
  Top Layer w0.254: U3.8 12.722,64.665 R1.2 C13.2
NetC14_2: C14.2 R2.2 U4.8 | length 3.2
  Top Layer w0.254: C14.2 R2.2 U4.8
NetC17_2: C17.2 R8.2 U6.8 | length 3.4
  Top Layer w0.254: U6.8 75.277,59.721 75.277,60.613 74.803,61.087 R8.2 C17.2
NetC18_2: C18.2 R7.2 U5.8 | length 3.2
  Top Layer w0.254: U5.8@14.564,42.412 14.564,40.808 R7.2
  Top Layer w0.5: C18.2 R7.2
NetC27_2: C27.2 R14.1 U7.28 | length 4.6
  Top Layer w0.254: U7.28 59.139,28.618 58.928,28.829 R14.1 59.925,30.588 60.052,30.588 C27.2
NetC33_1: C33.1 U8.20 | length 1.8
  Top Layer w0.254: C33.1 41.041,35.834 U8.20
NetC34_2: C34.2 U8.10 | length 1.9
  Top Layer w0.254: U8.10 48.74,35.334 C34.2
NetC36_1: C36.1 U9.1 | length 4.7
  Top Layer w0.5: U9.1 6.223,19.939 C36.1
NetC36_2: C36.2 D1.1 L4.1 U9.8 | length 8
  Top Layer w1: U9.8 9.211,20.038 9.211,24.412 D1.1 12.319,24.511 L4.1
NetGND1_0: GND1.0 H0.3 L3.1 | length 5
  Top Layer w0.254: H0.3@77.978,9.144 H0.3@78.08,9.042 ; H0.3 78.08,11.278 L3.1
  Bottom Layer w0.254: H0.3 78.09,9.261 78.09,6.487 GND1.0
NetH0_1: H0.1 R16.2 TX1.0 | length 18
  Top Layer w0.254: R16.2 60.071,9.779 62.039,7.81 71.539,7.81 H0.1
  Bottom Layer w0.254: H0.1 73.01,9.261 73.01,6.487 TX1.0
NetH0_2: H0.2 R17.2 RX1.0 | length 19.5
  Top Layer w0.254: R17.2 61.595,9.525 62.611,8.509 67.818,8.509 69.609,10.3 74.511,10.3 H0.2
  Bottom Layer w0.254: H0.2 75.55,9.261 75.55,6.487 RX1.0
NetH1_7: H1.7 L1.1 | length 2.2
  Top Layer w0.5: L1.1 79.792,55.336 81.911,55.336 H1.7
NetH2_7: H2.7 L2.1 | length 2.5
  Top Layer w0.3: H2.7@7.874,46.268 H2.7 7.897,46.355 L2.1
NetH4_2: H4.2 U10.1 VDDP.0 | length 26.5
  Bottom Layer w1: H4.2 29.362,9.246 29.362,6.406 VDDP.0@29.386,6.382
  Bottom Layer w2: U10.1 19.838,3.175 28.214,3.175 29.386,4.347 VDDP.0@29.386,6.382
"NetLED 1_1": "LED 1.1" R15.1 | length 1.4
  Top Layer w0.254: 56.951,66.659 R15.1
"NetLED 2_1": "LED 2.1" R18.1 | length 1.4
  Top Layer w0.254: 53.395,66.659 R18.1
NetR26_1: R26.1 R27.2 U9.4 | length 14
  Top Layer w0.254: U9.4 4.517,16.129 5.08,16.692 v1(5.08,16.764)
  Top Layer w0.5: v1(6.096,26.416) R27.2 R26.1
  Bottom Layer w0.254: v1(5.08,16.764) 5.08,25.4 v1(6.096,26.416)
NRST: C26.2 K1.1 R13.1 U7.7 | length 24.8
  Top Layer w0.254: U7.7 69.169,20.401 71.12,22.352 v1(71.628,22.352) 72.473,22.352 C26.2 R13.1 ; v1(84.836,20.193) 87.737,20.193 K1.1
  Bottom Layer w0.254: v1(71.628,22.352) 73.787,20.193 v1(84.836,20.193)
OUT1: H1.1 R4.2 U4.2 | length 8.6
  Top Layer w0.254: U4.2 76.566,45.608 76.454,45.72 76.454,46.99 76.581,47.117 77.473,47.117 R4.2
  Top Layer w1: R4.2@77.6,47.183 77.6,47.144 77.9,46.844 79.521,46.844 80.065,46.3 H1.1
OUT2: H1.3 R10.1 U6.3 | length 8.9
  Top Layer w0.254: U6.3 76.596,52.847 76.454,52.705 76.454,51.308 76.708,51.054 R10.1
  Top Layer w1: R10.1 77.877,50.777 79.144,50.777 80.621,49.3 H1.3
OUT3: H2.1 R3.2 U3.2 | length 8.1
  Top Layer w0.254: R3.2 12.316,54.737 13.208,54.737 13.462,54.991 13.462,55.536 13.372,55.626 13.372,56.75 13.391,56.769 U3.2@13.391,57.017
  Top Layer w1: H2.1 10.359,55.3 11.049,54.61 R3.2
OUT4: H2.3 R9.1 U5.3 | length 8.6
  Top Layer w0.254: R9.1 13.208,50.927 13.462,50.673 13.462,49.89 13.32,49.748 U5.3
  Top Layer w1: H2.3 9.168,52.3 10.475,50.993 12.123,50.993 R9.1
PGND: C3.2 C4.2 C5.2 C6.2 C9.2 C10.2 C37.2 C38.2 H4.1 PGND3.0 R28.2 U1.6 U1.7 U1.10 U1.14 U1.20 U1.28 U1.29 U2.6 U2.7 U2.10 U2.14 U2.20 U2.28 U2.29 U9.6 U9.9 | length 48.1
  Bottom Layer w1: 21.336,54.991 v1(21.336,55.499) v1(21.336,56.307) v1(21.336,57.023) 21.717,57.023 22.317,57.623 62.906,57.623 62.933,57.65 63.492,57.65 63.754,57.912 v1(63.754,58.166) ; PGND3.0@26.416,6.35 PGND3.0@26.607,6.541 ; PGND3.0 H4.1
  other v1: 13.081,15.748 11.049,15.875 12.065,15.875 6.096,16.002 7.112,16.002 7.874,16.637 5.842,17.272 6.604,17.272 7.366,17.272 5.842,18.034 6.604,18.034 7.366,18.034 5.842,18.796 6.604,18.796 7.366,18.796 5.842,20.828 3.048,21.082 4.191,21.209 3.556,21.717 6.223,21.717 4.191,21.971 3.048,22.352 3.937,22.86 6.223,22.86 25.347,40.351 21.336,40.386 22.225,40.386 23.114,40.386 23.876,40.386 24.638,40.386 26.162,40.386 21.336,41.402 22.479,41.402 24.511,41.402 25.654,41.402 26.416,41.402 23.597,41.438 21.336,53.848 21.336,54.61 64.643,58.166 65.532,58.166 66.421,58.166 67.31,58.166
RXD1: P1.1 U7.44 | length 15.6
  Top Layer w0.254: U7.44 55.985,19.401 56.134,19.252 56.134,5.969 P1.1
SPI1_CLK: MK1.4 R20.2 U7.19 | length 43.8
  Top Layer w0.254: MK1.4 R20.2 41.529,47.117 41.529,39.878 v1(42.799,38.608) ; U7.19 63.639,28.46 64.389,29.21 v1(64.389,33.655)
  Bottom Layer w0.254: v1(42.799,38.608) 45.339,36.068 48.514,36.068 49.657,34.925 63.119,34.925 v1(64.389,33.655)
SPI1_CS: MK1.3 U7.23 | length 41.6
  Top Layer w0.254: MK1.3 41.021,39.243 v1(42.418,37.846) ; v1(60.96,33.782) 62.357,32.385 62.357,29.845 61.639,29.127 U7.23
  Bottom Layer w0.254: v1(42.418,37.846) 44.831,35.433 48.26,35.433 49.911,33.782 v1(60.96,33.782)
SPI1_MISO: MK1.6 R22.2 U7.20 | length 35.6
  Top Layer w0.254: MK1.6 R22.2 v1(45.868,47.879) ; v1(53.086,45.593) 63.779,34.9 63.779,29.235 63.139,28.595 U7.20
  Bottom Layer w0.254: v1(45.868,47.879) 48.154,45.593 v1(53.086,45.593)
SPI1_MOSI: MK1.5 R21.2 U7.21 | length 36.6
  Top Layer w0.254: R21.2 MK1.5 ; v1(53.202,44.693) 53.224,44.693 63.373,34.544 63.373,29.591 62.639,28.857 U7.21
  Bottom Layer w0.254: v1(43.561,48.62) 47.484,44.696 53.199,44.696 v1(53.202,44.693)
SWCLK: P1.6 U7.50 | length 17.1
  Top Layer w0.254: U7.50 57.639,10.941 61.468,7.112 66.167,7.112 P1.6
SWDIO: P1.5 U7.49 | length 15.3
  Top Layer w0.254: U7.49 57.139,10.552 61.272,6.419 64.32,6.419 P1.5
TIM1_CH1: R5.7 U7.8 | length 33.8
  Top Layer w0.254: R5.7 60.855,46.101 60.706,45.952 60.706,44.323 71.628,33.401 71.628,23.495 69.034,20.901 U7.8
TIM1_CH2: R5.6 U7.9 | length 34.1
  Top Layer w0.254: R5.6 61.476,46.99 60.911,46.99 60.198,46.277 60.198,44.196 71.12,33.274 71.12,23.622 68.899,21.401 U7.9
TIM1_CH3: R5.5 U7.10 | length 34.4
  Top Layer w0.254: R5.5 60.401,47.701 59.69,46.99 59.69,43.942 70.591,33.041 70.591,23.855 68.637,21.901 U7.10
TIM3_CH1: R6.7 U7.38 | length 59.2
  Top Layer w0.254: R6.7 v1(29.426,55.791) v1@29.464,55.753 ; v1(51.678,50.281) 51.678,44.461 56.388,39.751 56.388,35.433 52.451,31.496 52.451,23.368 53.418,22.401 U7.38
  Bottom Layer w0.254: v1(29.426,55.791) 46.168,55.791 v1(51.678,50.281)
TIM3_CH2: R6.6 U7.18 | length 55.6
  Top Layer w0.254: R6.6 v1(29.21,54.991) ; v1(46.334,54.843) 46.355,54.864 48.895,54.864 52.959,50.8 52.959,46.609 65.077,34.491 65.077,29.157 64.139,28.219 U7.18
  Bottom Layer w0.254: v1(29.21,54.991) 46.091,54.991 46.24,54.843 v1(46.334,54.843)
TIM3_CH3: R6.5 U7.24 | length 53.4
  Top Layer w0.254: R6.5 29.248,54.191 v1(29.292,54.147) v1@29.337,54.102 ; v1(44.958,54.102) 48.641,54.102 52.324,50.419 52.324,44.577 57.093,39.808 57.093,36.506 61.976,31.623 61.976,30.226 61.139,29.389 U7.24
  Bottom Layer w0.254: v1(29.292,54.147) 29.315,54.124 44.936,54.124 v1(44.958,54.102)
TIM4_CH1: P3.1 U7.45 | length 15.1
  Top Layer w0.254: P3.1 48.387,9.144 50.719,11.476 50.719,16.302 53.318,18.901 U7.45
TIM4_CH2: P4.1 U7.46 | length 13.3
  Top Layer w0.254: P4.1 51.308,16.129 53.58,18.401 U7.46
TIM15_CH1: P6.1 U7.36 | length 23.8
  Top Layer w0.254: P6.1 47.879,12.827 v1(47.879,19.304) ; v1(53.005,23.873) 53.071,23.807 53.79,23.807 54.196,23.401 U7.36
  Bottom Layer w0.254: v1(47.879,19.304) 47.879,20.32 51.435,23.876 53.002,23.876 v1(53.005,23.873)
TIM15_CH2: P5.1 U7.37 | length 21.5
  Top Layer w0.254: P5.1 45.466,8.509 48.387,11.43 48.387,14.432 v1(48.433,14.478) ; v1(53.478,23.125) 53.55,23.125 53.774,22.901 U7.37
  Bottom Layer w0.254: v1(48.433,14.478) 48.433,19.677 51.87,23.114 53.467,23.114 v1(53.478,23.125)
TXD1: P1.2 U7.43 | length 16.5
  Top Layer w0.254: U7.43 56.045,19.901 56.664,19.282 56.664,19.199 56.642,19.177 56.642,6.477 57.785,5.334 P1.2
USART2_RX: R17.1 U7.57 | length 3.5
  Top Layer w0.254: U7.57 61.139,13.156 61.595,12.7 R17.1
USART2_TX: R16.1 U7.56 | length 3.5
  Top Layer w0.254: R16.1 60.071,12.7 60.639,13.268 U7.56
V3P3: C9.1 U1.15 U1.16 U1.17 | length 3.3
  Top Layer w0.254: C9.1 63.797,52.621 U1.16 ; U1.17 U1.16 ; U1.15 U1.16
V3P32: C10.1 U2.15 U2.16 U2.17 | length 3.3
  Top Layer w0.254: U2.17 U2.16 U2.15 25.901,48.775 C10.1
VDDA: C11.1 C12.1 C15.1 C16.1 C28.2 C29.2 C30.2 C46.1 C47.1 R14.2 U3.5 U3.7 U4.5 U4.7 U5.5 U5.7 U6.5 U6.7 U7.29 U12.5 | length 162.5
  Top Layer w0.243: C11.1 12.614,40.554 12.614,41.417 ; U5.5@12.614,42.412 12.614,41.417 ; U5.5 U5.5@12.67,43.084 ; U3.7 13.372,63.866 13.514,64.008 14.351,64.008 14.478,63.881 14.651,63.708 ; U5.7@13.914,42.412 13.914,41.417 13.772,41.275 12.756,41.275 12.614,41.417 ; U3.5 14.651,62.873 14.651,63.708 ; C15.1 14.834,64.491 14.834,63.891 14.651,63.708 ; U6.7 75.946,60.691 76.088,60.833 77.246,60.833 ; U6.5 77.246,60.833 ; v1(77.851,61.722) C16.1 77.246,61.565 77.246,60.833
  Top Layer w0.254: C30.2 C29.2 C28.2 ; U7.29 58.639,28.356 C28.2 ; R14.2 58.655,30.588 58.401,30.588 C28.2
  Top Layer w0.3: C11.1 11.684,40.513 11.43,40.259 11.43,37.592 12.573,36.449 v1(16.002,36.449) ; U5.5@12.67,43.084 12.066,43.688 7.62,43.688 5.842,45.466 5.842,56.388 7.62,58.166 10.541,58.166 13.372,60.997 U3.7 ; v1(74.041,36.576) C12.1 74.969,36.615 74.969,37.25 75.184,37.465 ; U4.5 75.266,37.547 75.184,37.465 ; v1(79.375,44.323) 76.566,41.514 U4.7 76.556,38.586 76.556,37.694 76.327,37.465 75.184,37.465
  Top Layer w0.4: U12.5 28.991,35.548 30.619,35.548 C47.1 33.105,35.433 33.376,35.163 33.376,34.849 v1(33.414,34.811) ; v1(53.213,29.591) C30.2
  Bottom Layer w0.3: v1(53.213,29.591) 67.056,29.591 v1(74.041,36.576) ; v1(77.851,61.722) 78.486,61.722 79.375,60.833 v1(79.375,44.323)
  Bottom Layer w0.4: v1(16.002,36.449) 31.776,36.449 38.634,29.591 v1(53.213,29.591)
VDDP: C37.1 C38.1 D2.2 U9.7 U10.2 | length 58.9
  Top Layer w1: U9.7 15.113,18.669 16.51,17.272 16.51,14.351
  Top Layer w1.5: D2.2 6.477,33.782 1.397,28.702 1.397,15.494 2.54,14.351 16.51,14.351 U10.2
pads on no net: H1.8 H1.9 H2.8 H2.9 R6.1 R6.8 U1.12 U1.13 U1.18 U1.19 U1.21 U2.12 U2.13 U2.18 U2.19 U2.21 U7.3 U7.4 U7.11 U7.25 U7.26 U7.30 U7.33 U7.34 U7.35 U7.52 U7.58 U7.59 U7.62 U8.2 U8.3 U8.4 U8.5 U8.14 U8.15 U8.16 U8.17 U8.19 U8.21 U8.22 U9.2 U9.3 U9.5 U10.3 U11.4 U12.4

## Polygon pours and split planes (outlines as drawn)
GND on Top Layer "GND_L01_P010" (solid, remove dead copper, pour order 10): 0,0 0,70 90,70 90,0
AGND on Top Layer "AGND_L01_P007" (solid, pour order 7): 78.105,45.847 78.105,34.925 76.581,33.401 75.565,33.401 72.771,36.195 72.771,43.561 75.057,45.847
AGND on Top Layer "AGND_L01_P005" (solid, pour order 5): 13.589,67.31 13.589,60.833 11.938,59.182 11.938,56.134 12.192,55.88 15.24,55.88 15.748,56.388 15.748,61.341 16.764,62.357 16.764,66.675 16.129,67.31
PGND on Top Layer "PGND_L01_P009" (solid, pour order 9): 8.636,23.368 13.716,18.288 13.716,14.986 2.794,14.986 2.032,15.748 2.032,23.368
AGND on Top Layer "AGND_L01_P006" (solid, pour order 6): 78.867,64.516 74.422,64.516 74.422,52.197 78.105,52.197 78.867,52.959 78.867,58.801
AGND on Top Layer "AGND_L01_P004" (solid, pour order 4): 12.192,49.403 15.24,49.403 17.399,47.244 17.399,38.1 16.51,37.211 12.446,37.211 11.43,38.227 11.43,45.72 12.192,46.482
PGND on Top Layer "PGND_L01_P001" (solid, pour order 1): 18.923,57.658 17.272,56.007 17.272,47.371 20.701,43.942 20.701,39.878 26.416,39.878 26.924,40.386 26.924,57.023 26.289,57.658
PGND on Top Layer "PGND_L01_P003" (solid, pour order 3): 71.501,59.69 71.501,55.499 72.644,54.356 72.644,47.625 69.342,44.323 65.024,44.323 64.516,44.831 64.516,49.149 62.992,50.673 62.992,58.547 64.135,59.69
GND on Bottom Layer "GND_L02_P011" (solid, remove dead copper, pour order 11): 0,0 0,70 90,70 90,0
PGND on Bottom Layer "PGND_L02_P008" (solid, pour order 8): 0,43.815 0.762,43.815 26.924,43.815 26.924,40.386 26.416,39.878 12.573,39.878 12.573,22.479 24.003,11.049 27.559,11.049 27.559,0.127 0,0.127

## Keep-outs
Keep-Out Layer:
  circle w0.1: c3,67 r1.25
  circle w0.1: c3,3 r1.25
  circle w0.1: c86,3 r1.25
  circle w0.1: c86,67 r1.25
  circle w0.1: c3,67 r2
  circle w0.1: c3,3 r2
  circle w0.1: c86,3 r2
  circle w0.1: c86,67 r2
  lines w0.1: 0,0 0,70 90,70 90,0 0,0

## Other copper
Top Layer:
  rectangle net PGND: 2.667,20.955 4.699,23.368
  rectangle net M_PWR: 16.002,46.99 17.018,50.038
  pour cut-out: 34.925,69.85 50.292,69.85 50.292,63.119 50.165,62.992 34.925,62.992
Bottom Layer:
  rectangle net PGND: 20.32,53.086 22.352,57.658
  rectangle net PGND: 62.992,57.15 68.453,59.055
  rectangle net AGND: 13.589,37.719 16.51,38.481
  rectangle net M_PWR: 15.621,46.99 17.272,50.165
  pour cut-out: 34.925,69.977 50.292,69.977 50.292,63.5 34.925,63.5

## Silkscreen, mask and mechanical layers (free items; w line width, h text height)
Top Overlay:
  text "OUTC" at 1.905,42.053 h1.52
  text "GND" at 84.424,42.053 h1.52
  text "3.3V" at 84.572,40.645 h1.52
  text "OUTB" at 1.905,40.569 h1.52
  text "SDA" at 84.565,39.225 h1.52
  text "OUTA" at 1.905,39.085 h1.52
  text "SCL" at 84.766,37.805 h1.52
  text "SCL" at 1.905,37.602 h1.52
  text "OUTA" at 83.585,36.384 h1.52
  text "SDA" at 1.905,36.118 h1.52
  text "OUTB" at 83.66,34.964 h1.52
  text "3.3V" at 1.905,34.647 h1.52
  text "OUTC" at 83.566,33.544 h1.52
  text "GND" at 1.905,33.163 h1.52
  text "FOC_DEVELOP_V05 2025.9" at 30.099,21.309 h2
  text "REST" at 85.455,20.701 h1.52 r90
  text "RXD" at 55.626,6.731 h1.52 r90
  text "TXD" at 58.293,6.731 h1.52 r90
  text "3.3V" at 60.689,6.731 h1.52 r90
  text "GND" at 63.484,6.731 h1.52 r90
  text "DIO" at 66.024,6.731 h1.52 r90
  text "CLK" at 68.691,6.731 h1.52 r90
Top Solder:
  circle w1: c3,3 r1.5
  circle w1: c3,67 r1.5
  circle w1: c86,67 r1.5
  circle w1: c86,3 r1.5
Bottom Solder:
  circle w1: c3,3 r1.5
  circle w1: c3,67 r1.5
  circle w1: c86,67 r1.5
  circle w1: c86,3 r1.5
